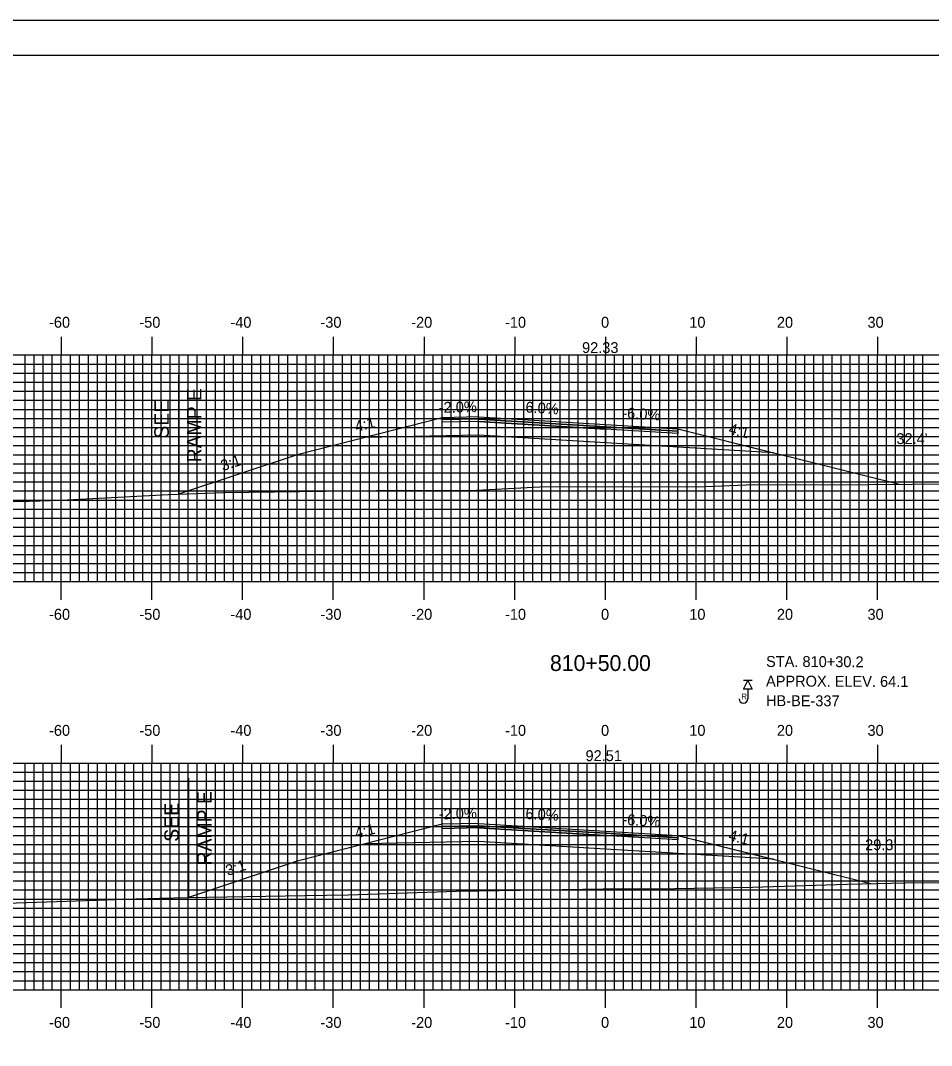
# Model space of a CAD drawing. Extents: x 1666 to 2009, y -1658 to -1438.
# Drawn here: x 1767.2 to 1867.6, y -1550.7 to -1437.7 of the extents above; entities that cross this region are included whole.
import ezdxf

# ---------------------------------------------------------------- set-up
doc = ezdxf.new("R2010")
doc.units = 0
for name, color, linetype in [('ANNOTATION', 7, 'Continuous'), ('BORDER', 7, 'Continuous'), ('BORING - REFUSAL', 7, 'Continuous'), ('D_Roadway_Centerline_Text', 7, 'Continuous'), ('D_Roadway_Edge_Shoulder', 7, 'Continuous'), ('D_Roadway_Edge_TW', 7, 'Continuous'), ('D_Roadway_Pavement', 7, 'Continuous'), ('D_Roadway_SlopeLines', 7, 'Continuous'), ('D_Roadway_SubGrade', 7, 'Continuous'), ('D_Text_Standard', 7, 'Continuous'), ('H_V ANNOTATION', 7, 'Continuous'), ('MAJOR', 7, 'Continuous'), ('MINOR', 7, 'Continuous'), ('PLOT BOUNDARY', 7, 'Continuous'), ('S_Roadway_Centerline', 7, 'Continuous')]:
    doc.layers.add(name, color=color, linetype=linetype)

msp = doc.modelspace()

# ---------------------------------------------------------------- linework, layer by layer
at = {"layer": 'ANNOTATION'}
for p, q in [((1817.67, -1481.44), (1813.67, -1481.52)), ((1817.67, -1481.69), (1813.67, -1481.77)), ((1817.67, -1483.44), (1805.17, -1483.69)), ((1817.67, -1526.26), (1813.67, -1526.34)), ((1817.67, -1526.51), (1813.67, -1526.59)), ((1817.67, -1528.26), (1805.17, -1528.51))]:
    msp.add_line(p, q, dxfattribs=at)
for points in [[(1813.67, -1481.52), (1797.67, -1485.6), (1784.6, -1489.95)], [(1817.67, -1481.94), (1813.67, -1482.02), (1813.67, -1481.52)], [(1813.67, -1526.34), (1797.67, -1530.42), (1785.71, -1534.41)], [(1817.67, -1526.76), (1813.67, -1526.84), (1813.67, -1526.34)]]:
    msp.add_lwpolyline(points, dxfattribs=at)
at = {"layer": 'BORDER'}
msp.add_lwpolyline([(1682.07, -1651.6), (2002.07, -1651.6), (2002.07, -1441.6), (1682.07, -1441.6)], close=True, dxfattribs=at)
at = {"layer": 'BORING - REFUSAL'}
for p, q in [((1847.85, -1510.5), (1846.89, -1510.5)), ((1847.37, -1511.46), (1847.37, -1512.52))]:
    msp.add_line(p, q, dxfattribs=at)
msp.add_lwpolyline([(1847.37, -1510.5), (1847.85, -1511.46), (1846.89, -1511.46)], close=True, dxfattribs=at)
msp.add_arc((1846.89, -1512.52), 0.485, 180, 0, dxfattribs=at)
at = {"layer": 'D_Roadway_Edge_Shoulder'}
for points in [[(1831.67, -1482.28), (1839.67, -1482.76), (1839.67, -1483.01), (1831.67, -1482.53)], [(1831.67, -1482.53), (1839.67, -1483.01), (1839.67, -1483.26), (1831.67, -1482.78)], [(1831.67, -1527.1), (1839.67, -1527.58), (1839.67, -1527.83), (1831.67, -1527.35)], [(1831.67, -1527.35), (1839.67, -1527.83), (1839.67, -1528.08), (1831.67, -1527.6)]]:
    msp.add_lwpolyline(points, close=True, dxfattribs=at)
at = {"layer": 'D_Roadway_Edge_TW'}
for points in [[(1817.67, -1481.44), (1831.67, -1482.28), (1831.67, -1482.53), (1817.67, -1481.69)], [(1817.67, -1526.26), (1831.67, -1527.1), (1831.67, -1527.35), (1817.67, -1526.51)]]:
    msp.add_lwpolyline(points, close=True, dxfattribs=at)
at = {"layer": 'D_Roadway_Pavement'}
for points in [[(1817.67, -1481.69), (1831.67, -1482.53), (1831.67, -1482.78), (1817.67, -1481.94)], [(1817.67, -1526.51), (1831.67, -1527.35), (1831.67, -1527.6), (1817.67, -1526.76)]]:
    msp.add_lwpolyline(points, close=True, dxfattribs=at)
for points in [[(1831.67, -1482.53), (1831.67, -1482.78)], [(1831.67, -1482.53), (1831.67, -1482.78)], [(1831.67, -1527.35), (1831.67, -1527.6)], [(1831.67, -1527.35), (1831.67, -1527.6)]]:
    msp.add_lwpolyline(points, dxfattribs=at)
at = {"layer": 'D_Roadway_SlopeLines'}
for points in [[(1839.67, -1482.76), (1864.1, -1488.86)], [(1839.67, -1527.58), (1860.93, -1532.89)]]:
    msp.add_lwpolyline(points, dxfattribs=at)
at = {"layer": 'D_Roadway_SubGrade'}
for p, q in [((1784.6, -1476.81), (1784.6, -1489.95)), ((1785.71, -1521.27), (1785.71, -1534.41))]:
    msp.add_line(p, q, dxfattribs=at)
for points in [[(1817.67, -1481.94), (1831.67, -1482.78), (1831.67, -1484.28), (1817.67, -1483.44)], [(1831.67, -1482.78), (1831.67, -1482.53), (1839.67, -1483.01), (1839.67, -1482.76), (1850.2, -1485.39), (1831.67, -1484.28)], [(1817.67, -1526.76), (1831.67, -1527.6), (1831.67, -1529.1), (1817.67, -1528.26)], [(1831.67, -1527.6), (1831.67, -1527.35), (1839.67, -1527.83), (1839.67, -1527.58), (1850.2, -1530.21), (1831.67, -1529.1)]]:
    msp.add_lwpolyline(points, close=True, dxfattribs=at)
at = {"layer": 'MAJOR'}
for p, q in [((1771.67, -1472.6), (1771.67, -1474.6)), ((1781.67, -1472.6), (1781.67, -1474.6)), ((1791.67, -1472.6), (1791.67, -1474.6)), ((1801.67, -1472.6), (1801.67, -1474.6)), ((1811.67, -1472.6), (1811.67, -1474.6)), ((1821.67, -1472.6), (1821.67, -1474.6)), ((1831.67, -1472.6), (1831.67, -1474.6)), ((1841.67, -1472.6), (1841.67, -1474.6)), ((1851.67, -1472.6), (1851.67, -1474.6)), ((1861.67, -1472.6), (1861.67, -1474.6)), ((1691.67, -1474.6), (1971.67, -1474.6)), ((1691.67, -1474.6), (1971.67, -1474.6)), ((1771.67, -1499.6), (1771.67, -1474.6)), ((1781.67, -1499.6), (1781.67, -1474.6)), ((1791.67, -1499.6), (1791.67, -1474.6)), ((1801.67, -1499.6), (1801.67, -1474.6)), ((1811.67, -1499.6), (1811.67, -1474.6)), ((1821.67, -1499.6), (1821.67, -1474.6)), ((1831.67, -1499.6), (1831.67, -1474.6)), ((1841.67, -1499.6), (1841.67, -1474.6)), ((1851.67, -1499.6), (1851.67, -1474.6)), ((1861.67, -1499.6), (1861.67, -1474.6)), ((1691.67, -1479.6), (1971.67, -1479.6)), ((1691.67, -1484.6), (1971.67, -1484.6)), ((1691.67, -1489.6), (1971.67, -1489.6)), ((1691.67, -1494.6), (1971.67, -1494.6)), ((1691.67, -1499.6), (1971.67, -1499.6)), ((1691.67, -1499.6), (1971.67, -1499.6)), ((1771.67, -1501.61), (1771.67, -1499.6)), ((1781.67, -1501.61), (1781.67, -1499.6)), ((1791.67, -1501.61), (1791.67, -1499.6)), ((1801.67, -1501.61), (1801.67, -1499.6)), ((1811.67, -1501.61), (1811.67, -1499.6)), ((1821.67, -1501.61), (1821.67, -1499.6)), ((1831.67, -1501.61), (1831.67, -1499.6)), ((1841.67, -1501.61), (1841.67, -1499.6)), ((1851.67, -1501.61), (1851.67, -1499.6)), ((1861.67, -1501.61), (1861.67, -1499.6)), ((1771.67, -1517.6), (1771.67, -1519.6)), ((1781.67, -1517.6), (1781.67, -1519.6)), ((1791.67, -1517.6), (1791.67, -1519.6)), ((1801.67, -1517.6), (1801.67, -1519.6)), ((1811.67, -1517.6), (1811.67, -1519.6)), ((1821.67, -1517.6), (1821.67, -1519.6)), ((1831.67, -1517.6), (1831.67, -1519.6)), ((1841.67, -1517.6), (1841.67, -1519.6)), ((1851.67, -1517.6), (1851.67, -1519.6)), ((1861.67, -1517.6), (1861.67, -1519.6)), ((1691.67, -1519.6), (1971.67, -1519.6)), ((1691.67, -1519.6), (1971.67, -1519.6)), ((1771.67, -1544.6), (1771.67, -1519.6)), ((1781.67, -1544.6), (1781.67, -1519.6)), ((1791.67, -1544.6), (1791.67, -1519.6)), ((1801.67, -1544.6), (1801.67, -1519.6)), ((1811.67, -1544.6), (1811.67, -1519.6)), ((1821.67, -1544.6), (1821.67, -1519.6)), ((1831.67, -1544.6), (1831.67, -1519.6)), ((1841.67, -1544.6), (1841.67, -1519.6)), ((1851.67, -1544.6), (1851.67, -1519.6)), ((1861.67, -1544.6), (1861.67, -1519.6)), ((1691.67, -1524.6), (1971.67, -1524.6)), ((1691.67, -1529.6), (1971.67, -1529.6)), ((1691.67, -1534.6), (1971.67, -1534.6)), ((1691.67, -1539.6), (1971.67, -1539.6)), ((1691.67, -1544.6), (1971.67, -1544.6)), ((1691.67, -1544.6), (1971.67, -1544.6)), ((1771.67, -1546.61), (1771.67, -1544.6)), ((1781.67, -1546.61), (1781.67, -1544.6)), ((1791.67, -1546.61), (1791.67, -1544.6)), ((1801.67, -1546.61), (1801.67, -1544.6)), ((1811.67, -1546.61), (1811.67, -1544.6)), ((1821.67, -1546.61), (1821.67, -1544.6)), ((1831.67, -1546.61), (1831.67, -1544.6)), ((1841.67, -1546.61), (1841.67, -1544.6)), ((1851.67, -1546.61), (1851.67, -1544.6)), ((1861.67, -1546.61), (1861.67, -1544.6))]:
    msp.add_line(p, q, dxfattribs=at)
at = {"layer": 'MINOR'}
for p, q in [((1767.67, -1499.6), (1767.67, -1474.6)), ((1768.67, -1499.6), (1768.67, -1474.6)), ((1769.67, -1499.6), (1769.67, -1474.6)), ((1770.67, -1499.6), (1770.67, -1474.6)), ((1772.67, -1499.6), (1772.67, -1474.6)), ((1773.67, -1499.6), (1773.67, -1474.6)), ((1774.67, -1499.6), (1774.67, -1474.6)), ((1775.67, -1499.6), (1775.67, -1474.6)), ((1776.67, -1499.6), (1776.67, -1474.6)), ((1777.67, -1499.6), (1777.67, -1474.6)), ((1778.67, -1499.6), (1778.67, -1474.6)), ((1779.67, -1499.6), (1779.67, -1474.6)), ((1780.67, -1499.6), (1780.67, -1474.6)), ((1782.67, -1499.6), (1782.67, -1474.6)), ((1783.67, -1499.6), (1783.67, -1474.6)), ((1784.67, -1499.6), (1784.67, -1474.6)), ((1785.67, -1499.6), (1785.67, -1474.6)), ((1786.67, -1499.6), (1786.67, -1474.6)), ((1787.67, -1499.6), (1787.67, -1474.6)), ((1788.67, -1499.6), (1788.67, -1474.6)), ((1789.67, -1499.6), (1789.67, -1474.6)), ((1790.67, -1499.6), (1790.67, -1474.6)), ((1792.67, -1499.6), (1792.67, -1474.6)), ((1793.67, -1499.6), (1793.67, -1474.6)), ((1794.67, -1499.6), (1794.67, -1474.6)), ((1795.67, -1499.6), (1795.67, -1474.6)), ((1796.67, -1499.6), (1796.67, -1474.6)), ((1797.67, -1499.6), (1797.67, -1474.6)), ((1798.67, -1499.6), (1798.67, -1474.6)), ((1799.67, -1499.6), (1799.67, -1474.6)), ((1800.67, -1499.6), (1800.67, -1474.6)), ((1802.67, -1499.6), (1802.67, -1474.6)), ((1803.67, -1499.6), (1803.67, -1474.6)), ((1804.67, -1499.6), (1804.67, -1474.6)), ((1805.67, -1499.6), (1805.67, -1474.6)), ((1806.67, -1499.6), (1806.67, -1474.6)), ((1807.67, -1499.6), (1807.67, -1474.6)), ((1808.67, -1499.6), (1808.67, -1474.6)), ((1809.67, -1499.6), (1809.67, -1474.6)), ((1810.67, -1499.6), (1810.67, -1474.6)), ((1812.67, -1499.6), (1812.67, -1474.6)), ((1813.67, -1499.6), (1813.67, -1474.6)), ((1814.67, -1499.6), (1814.67, -1474.6)), ((1815.67, -1499.6), (1815.67, -1474.6)), ((1816.67, -1499.6), (1816.67, -1474.6)), ((1817.67, -1499.6), (1817.67, -1474.6)), ((1818.67, -1499.6), (1818.67, -1474.6)), ((1819.67, -1499.6), (1819.67, -1474.6)), ((1820.67, -1499.6), (1820.67, -1474.6)), ((1822.67, -1499.6), (1822.67, -1474.6)), ((1823.67, -1499.6), (1823.67, -1474.6)), ((1824.67, -1499.6), (1824.67, -1474.6)), ((1825.67, -1499.6), (1825.67, -1474.6)), ((1826.67, -1499.6), (1826.67, -1474.6)), ((1827.67, -1499.6), (1827.67, -1474.6)), ((1828.67, -1499.6), (1828.67, -1474.6)), ((1829.67, -1499.6), (1829.67, -1474.6)), ((1830.67, -1499.6), (1830.67, -1474.6)), ((1832.67, -1499.6), (1832.67, -1474.6)), ((1833.67, -1499.6), (1833.67, -1474.6)), ((1834.67, -1499.6), (1834.67, -1474.6)), ((1835.67, -1499.6), (1835.67, -1474.6)), ((1836.67, -1499.6), (1836.67, -1474.6)), ((1837.67, -1499.6), (1837.67, -1474.6)), ((1838.67, -1499.6), (1838.67, -1474.6)), ((1839.67, -1499.6), (1839.67, -1474.6)), ((1840.67, -1499.6), (1840.67, -1474.6)), ((1842.67, -1499.6), (1842.67, -1474.6)), ((1843.67, -1499.6), (1843.67, -1474.6)), ((1844.67, -1499.6), (1844.67, -1474.6)), ((1845.67, -1499.6), (1845.67, -1474.6)), ((1846.67, -1499.6), (1846.67, -1474.6)), ((1847.67, -1499.6), (1847.67, -1474.6)), ((1848.67, -1499.6), (1848.67, -1474.6)), ((1849.67, -1499.6), (1849.67, -1474.6)), ((1850.67, -1499.6), (1850.67, -1474.6)), ((1852.67, -1499.6), (1852.67, -1474.6)), ((1853.67, -1499.6), (1853.67, -1474.6)), ((1854.67, -1499.6), (1854.67, -1474.6)), ((1855.67, -1499.6), (1855.67, -1474.6)), ((1856.67, -1499.6), (1856.67, -1474.6)), ((1857.67, -1499.6), (1857.67, -1474.6)), ((1858.67, -1499.6), (1858.67, -1474.6)), ((1859.67, -1499.6), (1859.67, -1474.6)), ((1860.67, -1499.6), (1860.67, -1474.6)), ((1862.67, -1499.6), (1862.67, -1474.6)), ((1863.67, -1499.6), (1863.67, -1474.6)), ((1864.67, -1499.6), (1864.67, -1474.6)), ((1865.67, -1499.6), (1865.67, -1474.6)), ((1866.67, -1499.6), (1866.67, -1474.6)), ((1691.67, -1475.6), (1971.67, -1475.6)), ((1691.67, -1476.6), (1971.67, -1476.6)), ((1691.67, -1477.6), (1971.67, -1477.6)), ((1691.67, -1478.6), (1971.67, -1478.6)), ((1691.67, -1480.6), (1971.67, -1480.6)), ((1691.67, -1481.6), (1971.67, -1481.6)), ((1691.67, -1482.6), (1971.67, -1482.6)), ((1691.67, -1483.6), (1971.67, -1483.6)), ((1691.67, -1485.6), (1971.67, -1485.6)), ((1691.67, -1486.6), (1971.67, -1486.6)), ((1691.67, -1487.6), (1971.67, -1487.6)), ((1691.67, -1488.6), (1971.67, -1488.6)), ((1691.67, -1490.6), (1971.67, -1490.6)), ((1691.67, -1491.6), (1971.67, -1491.6)), ((1691.67, -1492.6), (1971.67, -1492.6)), ((1691.67, -1493.6), (1971.67, -1493.6)), ((1691.67, -1495.6), (1971.67, -1495.6)), ((1691.67, -1496.6), (1971.67, -1496.6)), ((1691.67, -1497.6), (1971.67, -1497.6)), ((1691.67, -1498.6), (1971.67, -1498.6)), ((1767.67, -1544.6), (1767.67, -1519.6)), ((1768.67, -1544.6), (1768.67, -1519.6)), ((1769.67, -1544.6), (1769.67, -1519.6)), ((1770.67, -1544.6), (1770.67, -1519.6)), ((1772.67, -1544.6), (1772.67, -1519.6)), ((1773.67, -1544.6), (1773.67, -1519.6)), ((1774.67, -1544.6), (1774.67, -1519.6)), ((1775.67, -1544.6), (1775.67, -1519.6)), ((1776.67, -1544.6), (1776.67, -1519.6)), ((1777.67, -1544.6), (1777.67, -1519.6)), ((1778.67, -1544.6), (1778.67, -1519.6)), ((1779.67, -1544.6), (1779.67, -1519.6)), ((1780.67, -1544.6), (1780.67, -1519.6)), ((1782.67, -1544.6), (1782.67, -1519.6)), ((1783.67, -1544.6), (1783.67, -1519.6)), ((1784.67, -1544.6), (1784.67, -1519.6)), ((1785.67, -1544.6), (1785.67, -1519.6)), ((1786.67, -1544.6), (1786.67, -1519.6)), ((1787.67, -1544.6), (1787.67, -1519.6)), ((1788.67, -1544.6), (1788.67, -1519.6)), ((1789.67, -1544.6), (1789.67, -1519.6)), ((1790.67, -1544.6), (1790.67, -1519.6)), ((1792.67, -1544.6), (1792.67, -1519.6)), ((1793.67, -1544.6), (1793.67, -1519.6)), ((1794.67, -1544.6), (1794.67, -1519.6)), ((1795.67, -1544.6), (1795.67, -1519.6)), ((1796.67, -1544.6), (1796.67, -1519.6)), ((1797.67, -1544.6), (1797.67, -1519.6)), ((1798.67, -1544.6), (1798.67, -1519.6)), ((1799.67, -1544.6), (1799.67, -1519.6)), ((1800.67, -1544.6), (1800.67, -1519.6)), ((1802.67, -1544.6), (1802.67, -1519.6)), ((1803.67, -1544.6), (1803.67, -1519.6)), ((1804.67, -1544.6), (1804.67, -1519.6)), ((1805.67, -1544.6), (1805.67, -1519.6)), ((1806.67, -1544.6), (1806.67, -1519.6)), ((1807.67, -1544.6), (1807.67, -1519.6)), ((1808.67, -1544.6), (1808.67, -1519.6)), ((1809.67, -1544.6), (1809.67, -1519.6)), ((1810.67, -1544.6), (1810.67, -1519.6)), ((1812.67, -1544.6), (1812.67, -1519.6)), ((1813.67, -1544.6), (1813.67, -1519.6)), ((1814.67, -1544.6), (1814.67, -1519.6)), ((1815.67, -1544.6), (1815.67, -1519.6)), ((1816.67, -1544.6), (1816.67, -1519.6)), ((1817.67, -1544.6), (1817.67, -1519.6)), ((1818.67, -1544.6), (1818.67, -1519.6)), ((1819.67, -1544.6), (1819.67, -1519.6)), ((1820.67, -1544.6), (1820.67, -1519.6)), ((1822.67, -1544.6), (1822.67, -1519.6)), ((1823.67, -1544.6), (1823.67, -1519.6)), ((1824.67, -1544.6), (1824.67, -1519.6)), ((1825.67, -1544.6), (1825.67, -1519.6)), ((1826.67, -1544.6), (1826.67, -1519.6)), ((1827.67, -1544.6), (1827.67, -1519.6)), ((1828.67, -1544.6), (1828.67, -1519.6)), ((1829.67, -1544.6), (1829.67, -1519.6)), ((1830.67, -1544.6), (1830.67, -1519.6)), ((1832.67, -1544.6), (1832.67, -1519.6)), ((1833.67, -1544.6), (1833.67, -1519.6)), ((1834.67, -1544.6), (1834.67, -1519.6)), ((1835.67, -1544.6), (1835.67, -1519.6)), ((1836.67, -1544.6), (1836.67, -1519.6)), ((1837.67, -1544.6), (1837.67, -1519.6)), ((1838.67, -1544.6), (1838.67, -1519.6)), ((1839.67, -1544.6), (1839.67, -1519.6)), ((1840.67, -1544.6), (1840.67, -1519.6)), ((1842.67, -1544.6), (1842.67, -1519.6)), ((1843.67, -1544.6), (1843.67, -1519.6)), ((1844.67, -1544.6), (1844.67, -1519.6)), ((1845.67, -1544.6), (1845.67, -1519.6)), ((1846.67, -1544.6), (1846.67, -1519.6)), ((1847.67, -1544.6), (1847.67, -1519.6)), ((1848.67, -1544.6), (1848.67, -1519.6)), ((1849.67, -1544.6), (1849.67, -1519.6)), ((1850.67, -1544.6), (1850.67, -1519.6)), ((1852.67, -1544.6), (1852.67, -1519.6)), ((1853.67, -1544.6), (1853.67, -1519.6)), ((1854.67, -1544.6), (1854.67, -1519.6)), ((1855.67, -1544.6), (1855.67, -1519.6)), ((1856.67, -1544.6), (1856.67, -1519.6)), ((1857.67, -1544.6), (1857.67, -1519.6)), ((1858.67, -1544.6), (1858.67, -1519.6)), ((1859.67, -1544.6), (1859.67, -1519.6)), ((1860.67, -1544.6), (1860.67, -1519.6)), ((1862.67, -1544.6), (1862.67, -1519.6)), ((1863.67, -1544.6), (1863.67, -1519.6)), ((1864.67, -1544.6), (1864.67, -1519.6)), ((1865.67, -1544.6), (1865.67, -1519.6)), ((1866.67, -1544.6), (1866.67, -1519.6)), ((1691.67, -1520.6), (1971.67, -1520.6)), ((1691.67, -1521.6), (1971.67, -1521.6)), ((1691.67, -1522.6), (1971.67, -1522.6)), ((1691.67, -1523.6), (1971.67, -1523.6)), ((1691.67, -1525.6), (1971.67, -1525.6)), ((1691.67, -1526.6), (1971.67, -1526.6)), ((1691.67, -1527.6), (1971.67, -1527.6)), ((1691.67, -1528.6), (1971.67, -1528.6)), ((1691.67, -1530.6), (1971.67, -1530.6)), ((1691.67, -1531.6), (1971.67, -1531.6)), ((1691.67, -1532.6), (1971.67, -1532.6)), ((1691.67, -1533.6), (1971.67, -1533.6)), ((1691.67, -1535.6), (1971.67, -1535.6)), ((1691.67, -1536.6), (1971.67, -1536.6)), ((1691.67, -1537.6), (1971.67, -1537.6)), ((1691.67, -1538.6), (1971.67, -1538.6)), ((1691.67, -1540.6), (1971.67, -1540.6)), ((1691.67, -1541.6), (1971.67, -1541.6)), ((1691.67, -1542.6), (1971.67, -1542.6)), ((1691.67, -1543.6), (1971.67, -1543.6))]:
    msp.add_line(p, q, dxfattribs=at)
at = {"layer": 'PLOT BOUNDARY'}
msp.add_lwpolyline([(1665.89, -1657.72), (2005.89, -1657.72), (2005.89, -1437.72), (1665.89, -1437.72)], close=True, dxfattribs=at)
at = {"layer": 'S_Roadway_Centerline'}
for points in [[(1691.67, -1492.34), (1699.81, -1492.38), (1701.19, -1492.36), (1702.67, -1492.28), (1717.58, -1491.83), (1720.22, -1491.81), (1733.87, -1491.74), (1748.02, -1490.83), (1751.46, -1490.79), (1754.73, -1490.74), (1766.98, -1490.75), (1771.61, -1490.61), (1783.49, -1489.99), (1789.56, -1489.78), (1809.24, -1489.53), (1816.75, -1489.54), (1824.44, -1489.13), (1833.5, -1489.1), (1841.83, -1489.15), (1848.09, -1488.88), (1855.96, -1488.91), (1865.49, -1488.85), (1876.3, -1488.74)], [(1691.67, -1536.67), (1711.89, -1536.34), (1716.2, -1536.19), (1719.95, -1536.08), (1732.83, -1535.88), (1748.72, -1535.24), (1749.56, -1535.21), (1753.49, -1535.18), (1764.64, -1535.1), (1765.63, -1535.07), (1779.94, -1534.59), (1782.5, -1534.5), (1785.63, -1534.41), (1798.54, -1534.19), (1803.32, -1534.13), (1815.26, -1533.72), (1824.65, -1533.57), (1831.43, -1533.46), (1839.32, -1533.42), (1847.88, -1533.28), (1858.32, -1532.95), (1864.78, -1532.81), (1875.82, -1532.7)]]:
    msp.add_lwpolyline(points, dxfattribs=at)

# ---------------------------------------------------------------- texts
at = {"layer": 'ANNOTATION'}
for s, height, rotation, p in [('RAMP E', 1.6, 90, (1787.13, -1486.45)), ('SEE', 1.6, 90, (1783.53, -1483.83)), ('-2.0%', 1.2, 1.1458, (1813.31, -1480.99)), ('6.0%', 1.2, 356.5664, (1822.83, -1480.94)), ('-6.0%', 1.2, 356.5664, (1833.51, -1481.58)), ('4:1', 1.2, 14.0362, (1804.21, -1483.1)), ('4:1', 1.2, 345.9638, (1845.18, -1483.27)), ('3:1', 1.2, 18.4348, (1789.48, -1487.42)), ('RAMP E', 1.6, 90, (1788.24, -1530.9)), ('SEE', 1.6, 90, (1784.64, -1528.28)), ('-2.0%', 1.2, 1.1458, (1813.31, -1525.81)), ('6.0%', 1.2, 356.5664, (1822.83, -1525.76)), ('-6.0%', 1.2, 356.5664, (1833.51, -1526.4)), ('4:1', 1.2, 14.0362, (1804.21, -1527.92)), ('4:1', 1.2, 345.9638, (1845.18, -1528.09)), ('3:1', 1.2, 18.4348, (1790.03, -1532.06))]:
    msp.add_text(s, height=height, rotation=rotation, dxfattribs=at).set_placement(p)
at = {"layer": 'BORING - REFUSAL'}
for s, p in [('STA. 810+30.2', (1849.39, -1509)), ('APPROX. ELEV. 64.1', (1849.38, -1511.16)), ('HB-BE-337', (1849.38, -1513.32))]:
    msp.add_text(s, height=1.2, rotation=359.8142, dxfattribs=at).set_placement(p)
msp.add_text('R', height=0.64, dxfattribs=at).set_placement((1846.66, -1512.58))
at = {"layer": 'D_Roadway_Centerline_Text'}
for s, p in [('92.33', (1829.1, -1474.39)), ('92.51', (1829.48, -1519.39))]:
    msp.add_text(s, height=1.2, dxfattribs=at).set_placement(p)
at = {"layer": 'D_Text_Standard'}
for s, p in [("32.4'", (1863.76, -1484.43)), ("29.3'", (1860.31, -1529.21))]:
    msp.add_text(s, height=1.2, dxfattribs=at).set_placement(p)
at = {"layer": 'H_V ANNOTATION'}
for s, height, p in [('-60', 1.2, (1770.32, -1471.6)), ('-50', 1.2, (1780.28, -1471.6)), ('-40', 1.2, (1790.32, -1471.6)), ('-30', 1.2, (1800.25, -1471.6)), ('-20', 1.2, (1810.26, -1471.6)), ('-10', 1.2, (1820.6, -1471.6)), ('0', 1.2, (1831.19, -1471.6)), ('10', 1.2, (1840.92, -1471.6)), ('20', 1.2, (1850.58, -1471.6)), ('30', 1.2, (1860.57, -1471.6)), ('-60', 1.2, (1770.32, -1503.8)), ('-50', 1.2, (1780.28, -1503.8)), ('-40', 1.2, (1790.32, -1503.8)), ('-30', 1.2, (1800.25, -1503.8)), ('-20', 1.2, (1810.26, -1503.8)), ('-10', 1.2, (1820.6, -1503.8)), ('0', 1.2, (1831.19, -1503.8)), ('10', 1.2, (1840.92, -1503.8)), ('20', 1.2, (1850.58, -1503.8)), ('30', 1.2, (1860.57, -1503.8)), ('810+50.00', 1.75, (1825.56, -1509.45)), ('-60', 1.2, (1770.32, -1516.6)), ('-50', 1.2, (1780.28, -1516.6)), ('-40', 1.2, (1790.32, -1516.6)), ('-30', 1.2, (1800.25, -1516.6)), ('-20', 1.2, (1810.26, -1516.6)), ('-10', 1.2, (1820.6, -1516.6)), ('0', 1.2, (1831.19, -1516.6)), ('10', 1.2, (1840.92, -1516.6)), ('20', 1.2, (1850.58, -1516.6)), ('30', 1.2, (1860.57, -1516.6)), ('-60', 1.2, (1770.32, -1548.8)), ('-50', 1.2, (1780.28, -1548.8)), ('-40', 1.2, (1790.32, -1548.8)), ('-30', 1.2, (1800.25, -1548.8)), ('-20', 1.2, (1810.26, -1548.8)), ('-10', 1.2, (1820.6, -1548.8)), ('0', 1.2, (1831.19, -1548.8)), ('10', 1.2, (1840.92, -1548.8)), ('20', 1.2, (1850.58, -1548.8)), ('30', 1.2, (1860.57, -1548.8))]:
    msp.add_text(s, height=height, dxfattribs=at).set_placement(p)

doc.saveas('drawing.dxf')
